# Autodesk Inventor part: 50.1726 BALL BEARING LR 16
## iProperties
Created: 2009-01
Part Number: 50.1726 BALL BEARING LR 16
Document SubType Name: Modeling
Designer: Administrator
Density: 7.85 g/cm^3
Material: Steel
Mass: 257.028 g
Surface Area: 91.7369 cm^2
Volume: 32.7424 cm^3
Author: Administrator
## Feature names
1. Base1
